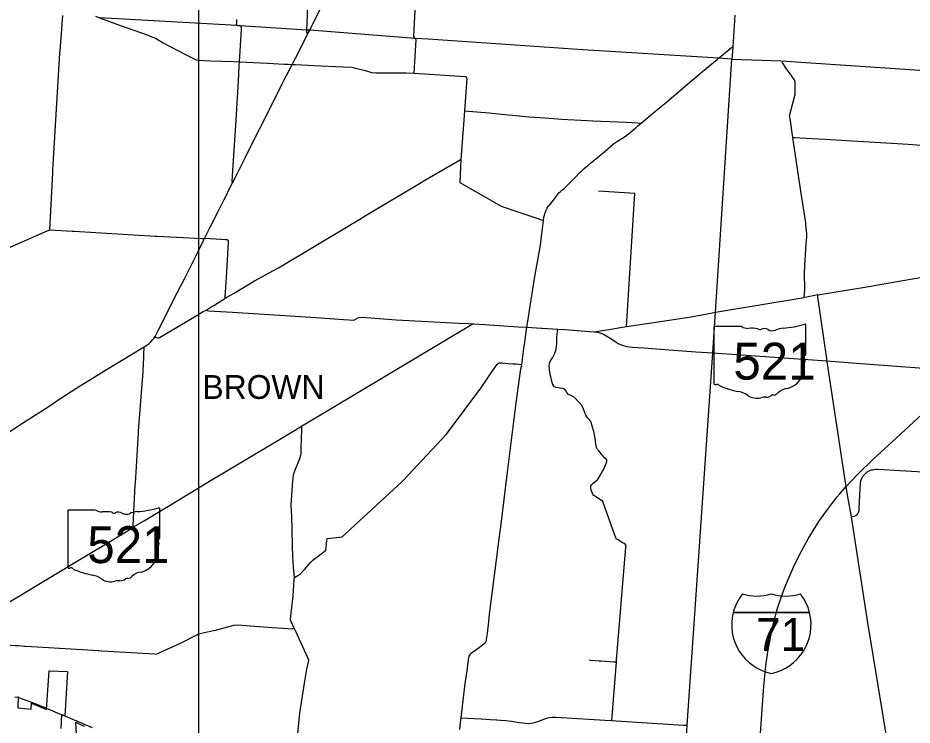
# Model space of a CAD drawing. Extents: x 1729596 to 1925846, y 659247 to 911751.
# Drawn here: x 1821771 to 1855559, y 833985 to 860705 of the extents above; entities that cross this region are included whole.
import ezdxf

# ---------------------------------------------------------------- set-up
doc = ezdxf.new("R2010")
doc.units = 0
for name, color, linetype in [('GM_X_Corporation', 7, 'Continuous'), ('GM_X_County', 7, 'Continuous'), ('GM_X_County_Road', 7, 'Continuous'), ('GM_X_Interstate_Route', 7, 'Continuous'), ('GM_X_Interstate_Shield', 7, 'Continuous'), ('GM_X_State_Route', 7, 'Continuous'), ('GM_X_State_Shield', 7, 'Continuous'), ('GM_X_Township', 7, 'Continuous'), ('GM_X_Township_Road', 7, 'Continuous'), ('GM_X_Township_Text', 7, 'Continuous'), ('GM_X_US_Route', 7, 'Continuous'), ('SH_Data', 7, 'Continuous')]:
    doc.layers.add(name, color=color, linetype=linetype)

msp = doc.modelspace()

# ---------------------------------------------------------------- linework, layer by layer
at = {"layer": 'GM_X_Corporation'}
for points in [[(1821656, 835046), (1821781, 835050), (1821769, 834633), (1822268, 834587), (1822281, 834808), (1822854, 834577), (1822956, 836039), (1823645, 836005), (1823540, 834336), (1823415, 834383), (1823397, 833851)], [(1824058, 832202), (1823955, 834094), (1824182, 833983), (1824200, 833986), (1824290, 833942)]]:
    msp.add_lwpolyline(points, dxfattribs=at)
at = {"layer": 'GM_X_County'}
msp.add_lwpolyline([(1848864, 860810), (1848787, 859601), (1848752, 859146), (1850615, 859080), (1861827, 858324)], dxfattribs=at)
at = {"layer": 'GM_X_County_Road'}
for points in [[(1824699, 860768), (1824857, 860710), (1825612, 860430), (1826656, 860059), (1826853, 859982), (1826971, 859934), (1827258, 859768), (1827710, 859527), (1828254, 859247), (1828432, 859153), (1828513, 859123), (1828584, 859112), (1829052, 859088), (1829917, 859051), (1830145, 859048), (1831204, 858991), (1831412, 858982), (1831846, 858956), (1831978, 858953), (1832140, 858950)], [(1848293, 859218), (1848788, 859619)], [(1832140, 858950), (1832225, 858943), (1832265, 858939), (1832961, 858909), (1834057, 858860), (1834388, 858837), (1834514, 858807), (1834697, 858768), (1834897, 858714), (1835014, 858675), (1835136, 858637), (1835294, 858625), (1835692, 858625), (1836196, 858623), (1836448, 858626), (1836739, 858621)], [(1841006, 849018), (1841051, 849314), (1841101, 849645), (1841295, 850857), (1841512, 852119), (1841560, 852444), (1841625, 853051), (1841645, 853178), (1841666, 853257), (1841678, 853296), (1841734, 853436), (1841775, 853522), (1841811, 853578), (1841852, 853630), (1841955, 853751), (1842050, 853872), (1842120, 853970), (1842174, 854044), (1842213, 854090), (1842257, 854132), (1842328, 854190), (1842398, 854247), (1842454, 854298), (1842569, 854408), (1842835, 854682), (1843009, 854858), (1843082, 854926), (1843184, 855026), (1843290, 855116), (1843408, 855218), (1843743, 855499), (1843955, 855674), (1844282, 855947), (1844355, 856000), (1844431, 856051), (1844597, 856149), (1844696, 856217), (1844777, 856277), (1844977, 856441), (1845142, 856580), (1845198, 856628), (1845320, 856733), (1845665, 857022), (1846093, 857374), (1846284, 857524), (1846382, 857614), (1847073, 858199), (1847645, 858684), (1848208, 859149), (1848243, 859177), (1848285, 859211), (1848293, 859218)], [(1852342, 847746), (1852332, 847819), (1852002, 850172), (1851992, 850242), (1851578, 850159), (1851485, 850140), (1851503, 850457), (1851507, 850519), (1851495, 850994), (1851492, 851085), (1851506, 851296), (1851510, 851368), (1851545, 851947), (1851548, 852007), (1851578, 852429), (1851584, 852517), (1851577, 852569), (1851568, 852637), (1851545, 852900), (1851540, 852956), (1851400, 853843), (1851390, 853908), (1851065, 856102), (1851052, 856192), (1850945, 856903), (1850930, 857004), (1851117, 857720), (1851136, 857792), (1851143, 857929), (1851137, 858286), (1851111, 858362), (1851070, 858431), (1851029, 858488), (1850952, 858587), (1850847, 858724), (1850809, 858773), (1850694, 858953), (1850650, 859027)], [(1836739, 858621), (1838675, 858491), (1838704, 858476), (1838715, 858460)], [(1838715, 858460), (1838725, 858446), (1838731, 858409), (1838644, 857189), (1838612, 856680), (1838509, 855352), (1838468, 854485), (1840033, 853588), (1840704, 853369), (1840998, 853268), (1841304, 853162), (1841625, 853051)], [(1851992, 850242), (1853696, 850524), (1855503, 850836), (1856828, 851059), (1859214, 851472), (1860807, 851754), (1861908, 851967)], [(1848128, 849585), (1851485, 850140)], [(1827483, 848845), (1828569, 849486), (1828773, 849606), (1828890, 849668)], [(1828890, 849668), (1828890, 849668), (1828924, 849648), (1828977, 849643), (1829879, 849585), (1833037, 849389), (1834076, 849311), (1834469, 849288), (1834642, 849380), (1834781, 849392), (1836063, 849299), (1838431, 849174), (1838783, 849153), (1838998, 849141)], [(1843595, 848838), (1843637, 848852), (1843852, 848894), (1844102, 848937), (1844768, 849049), (1846050, 849232), (1847118, 849400), (1847685, 849497), (1848128, 849585)], [(1846971, 832575), (1846971, 832575), (1847065, 833986), (1848030, 848046), (1848128, 849585)], [(1826954, 848664), (1826976, 848639), (1827002, 848628), (1827054, 848615), (1827084, 848617), (1827126, 848635), (1827483, 848845)], [(1838466, 833825), (1838487, 833985), (1838519, 834265), (1838567, 834705), (1838674, 835560), (1838743, 836040), (1838773, 836253), (1838796, 836429), (1838814, 836551), (1838826, 836590), (1838844, 836629), (1838867, 836664), (1838885, 836685), (1838954, 836740), (1839072, 836824), (1839157, 836890), (1839273, 836974), (1839413, 837081), (1839426, 837095), (1839438, 837110), (1839458, 837143), (1839466, 837161), (1839472, 837179), (1839477, 837198), (1839478, 837221), (1839510, 837440), (1839538, 837684), (1839547, 837760), (1839596, 838176), (1839967, 841111), (1840035, 841581), (1840259, 843439), (1840381, 844450), (1840596, 846166), (1840736, 847171), (1840762, 847354), (1840807, 847615), (1840906, 848311), (1840922, 848444), (1840955, 848656), (1841006, 849018)], [(1854821, 832136), (1854806, 832276), (1853927, 837618), (1853916, 837681), (1853270, 841855), (1853135, 842607), (1853071, 843001), (1853019, 843312), (1852359, 847640), (1852342, 847746)], [(1824834, 836804), (1824939, 836797), (1826941, 836673), (1827000, 836670), (1827915, 837079), (1827969, 837103), (1828528, 837401), (1828591, 837434), (1829159, 837555), (1829234, 837570), (1829847, 837731), (1829932, 837765), (1830068, 837770), (1831380, 837679), (1831789, 837651), (1832132, 837627), (1832164, 837633), (1832207, 837647), (1832086, 837925), (1832077, 837968), (1832081, 838107), (1832167, 838864), (1832211, 839479), (1832217, 839559), (1832354, 839640), (1832420, 839679), (1832530, 839793), (1832596, 839862), (1832843, 840137), (1832910, 840211), (1833329, 840531), (1833411, 840594), (1833446, 840962), (1833453, 841041), (1833926, 841092), (1834029, 841103), (1836280, 843180), (1836334, 843229), (1837952, 844970), (1838003, 845024), (1839263, 846719), (1839296, 846763), (1839657, 847296), (1839829, 847544), (1839890, 847618), (1839921, 847646), (1839949, 847661), (1839978, 847670), (1839994, 847672), (1840065, 847668), (1840312, 847648), (1840471, 847640), (1840580, 847631), (1840807, 847615)], [(1820825, 837049), (1820913, 837042), (1821680, 836994), (1821777, 836987), (1822028, 836972), (1822074, 836969)], [(1822074, 836969), (1824417, 836829)], [(1824417, 836829), (1824803, 836806), (1824834, 836804), (1824834, 836804)]]:
    msp.add_lwpolyline(points, dxfattribs=at)
at = {"layer": 'GM_X_Interstate_Route'}
for points in [[(1853497, 843457), (1854091, 844035), (1854810, 844689), (1856408, 846161), (1857196, 846884), (1857351, 847028)], [(1852825, 842723), (1853071, 843001), (1853486, 843445), (1853497, 843457)], [(1849960, 835440), (1849991, 835852), (1850027, 836225), (1850112, 836751), (1850219, 837345), (1850270, 837606), (1850358, 837993), (1850490, 838443), (1850609, 838810), (1850743, 839153), (1850946, 839662), (1851071, 839958), (1851303, 840416), (1851627, 841020), (1852032, 841680), (1852294, 842043), (1852715, 842598), (1852825, 842723)], [(1849232, 825823), (1849312, 826884), (1849342, 827283), (1849536, 829857), (1849737, 832422), (1849949, 835289), (1849960, 835440)]]:
    msp.add_lwpolyline(points, dxfattribs=at)
at = {"layer": 'GM_X_Interstate_Shield'}
for p, q in [((1848799, 838237), (1851684, 838237)), ((1851684, 838237), (1848799, 838237)), ((1851684, 838237), (1848799, 838237)), ((1848799, 838237), (1851684, 838237)), ((1851684, 838237), (1848799, 838237)), ((1851684, 838237), (1848799, 838237))]:
    msp.add_line(p, q, dxfattribs=at)
for centre, start, end in [((1850616, 837777), 141.669, 165.8066), ((1850616, 837777), 141.669, 165.8066), ((1849693, 840733), 253.0091, 286.9909), ((1849693, 840733), 253.0091, 286.9909), ((1850789, 840733), 253.0091, 286.9909), ((1850789, 840733), 253.0091, 286.9909), ((1849866, 837777), 14.1934, 38.331), ((1849866, 837777), 14.1934, 38.331), ((1850616, 837777), 165.8066, 258.463), ((1850616, 837777), 165.8066, 258.463), ((1849866, 837777), 281.537, 14.1934), ((1849866, 837777), 281.537, 14.1934)]:
    msp.add_arc(centre, 1875, start, end, dxfattribs=at)
at = {"layer": 'GM_X_State_Route'}
for points in [[(1824240, 840319), (1825270, 840939), (1826096, 841440), (1826142, 841474), (1826514, 841694), (1827976, 842576), (1829017, 843200), (1831719, 844816), (1832490, 845282), (1838868, 849097), (1838914, 849121), (1838998, 849141), (1839418, 849116)], [(1839418, 849116), (1839597, 849106), (1840678, 849037), (1841006, 849018)], [(1841006, 849018), (1841537, 848985), (1841586, 848982)], [(1841586, 848982), (1842167, 848948), (1842431, 848928)], [(1842431, 848928), (1843370, 848858), (1843543, 848843)], [(1843543, 848843), (1843595, 848838), (1843668, 848826), (1843754, 848804), (1843796, 848791), (1843824, 848782), (1843899, 848751), (1843959, 848721), (1844210, 848561), (1844336, 848473), (1844448, 848406), (1844608, 848336), (1844771, 848292), (1844988, 848267), (1845431, 848234), (1846221, 848181), (1847382, 848093), (1848030, 848046), (1852342, 847746), (1853462, 847664), (1857695, 847346)], [(1820468, 838053), (1820655, 838166), (1821648, 838759), (1824240, 840319)]]:
    msp.add_lwpolyline(points, dxfattribs=at)
at = {"layer": 'GM_X_State_Shield'}
for p, q in [((1851549, 847988), (1851549, 849093)), ((1851549, 847988), (1851549, 849093)), ((1848068, 849005), (1848068, 846891)), ((1848068, 849005), (1848068, 846891)), ((1849122, 849041), (1848102, 849041)), ((1849122, 849041), (1848102, 849041)), ((1851548, 847988), (1851549, 847988)), ((1851548, 847988), (1851549, 847988)), ((1823657, 842070), (1823657, 839957)), ((1823657, 842070), (1823657, 839957)), ((1824710, 842107), (1823691, 842107)), ((1824710, 842107), (1823691, 842107)), ((1827137, 841053), (1827137, 842159)), ((1827137, 841053), (1827137, 842159)), ((1827137, 841054), (1827137, 841053)), ((1827137, 841054), (1827137, 841053))]:
    msp.add_line(p, q, dxfattribs=at)
for centre, major_axis, start_param, end_param in [((1850309, 851922), (3691, 0), 4.814394, 5.042369), ((1850309, 851922), (3691, 0), 4.814394, 5.042369), ((1851510, 849098), (38.7, 0), 6.141152, 7.989035), ((1851510, 849098), (38.7, 0), 6.141152, 7.989035), ((1848108, 849009), (40.3, 0), 1.712693, 3.28349), ((1848108, 849009), (40.3, 0), 1.712693, 3.28349), ((1849364, 849286), (391, 0), 4.042523, 4.731795), ((1849364, 849286), (391, 0), 4.042523, 4.731795), ((1849494, 847855), (1404, 0), 1.404758, 1.657858), ((1849494, 847855), (1404, 0), 1.404758, 1.657858), ((1849813, 849020), (113, 0), 3.836095, 5.185415), ((1849813, 849020), (113, 0), 3.836095, 5.185415), ((1849978, 848776), (235, 0), 0.950623, 2.079405), ((1849978, 848776), (235, 0), 0.950623, 2.079405), ((1850281, 849111), (282, 0), 4.081561, 5.145723), ((1850281, 849111), (282, 0), 4.081561, 5.145723), ((1850780, 848395), (743, 0), 1.699011, 2.107814), ((1850780, 848395), (743, 0), 1.699011, 2.107814), ((1851540, 847907), (60, 0), 1.883978, 3.671073), ((1851540, 847907), (60, 0), 1.883978, 3.671073), ((1851158, 847767), (360, 0), 5.934695, 6.695948), ((1851158, 847767), (360, 0), 5.934695, 6.695948), ((1851507, 847984), (41.5, 0), 5.05454, 6.418171), ((1851507, 847984), (41.5, 0), 5.05454, 6.418171), ((1850515, 847385), (923, 0), 5.101752, 6.440018), ((1850515, 847385), (923, 0), 5.101752, 6.440018), ((1851687, 847525), (262, 0), 2.387724, 3.262537), ((1851687, 847525), (262, 0), 2.387724, 3.262537), ((1848108, 846887), (40.7, 0), 3.00124, 4.508301), ((1848108, 846887), (40.7, 0), 3.00124, 4.508301), ((1848115, 847103), (310, 0), 4.665946, 4.897461), ((1848115, 847103), (310, 0), 4.665946, 4.897461), ((1848178, 846769), (112, 0), 0.519207, 1.627899), ((1848178, 846769), (112, 0), 0.519207, 1.627899), ((1849591, 848668), (2665, 0), 4.195997, 4.488961), ((1849591, 848668), (2665, 0), 4.195997, 4.488961), ((1848797, 845942), (834, 0), 0.823519, 1.323587), ((1848797, 845942), (834, 0), 0.823519, 1.323587), ((1849699, 846759), (529, 0), 4.026481, 4.996735), ((1849699, 846759), (529, 0), 4.026481, 4.996735), ((1850043, 846601), (282, 0), 4.691044, 5.507374), ((1850043, 846601), (282, 0), 4.691044, 5.507374), ((1850298, 846396), (79.4, 0), 1.147584, 2.315152), ((1850298, 846396), (79.4, 0), 1.147584, 2.315152), ((1850264, 846686), (298, 0), 4.937069, 5.64225), ((1850264, 846686), (298, 0), 4.937069, 5.64225), ((1850905, 846298), (506, 0), 1.647645, 2.488434), ((1850905, 846298), (506, 0), 1.647645, 2.488434), ((1850004, 846028), (435, 0), 1.495662, 1.94098), ((1850004, 846028), (435, 0), 1.495662, 1.94098), ((1823697, 842075), (40.3, 0), 1.712693, 3.28349), ((1823697, 842075), (40.3, 0), 1.712693, 3.28349), ((1824953, 842352), (391, 0), 4.042523, 4.731795), ((1824953, 842352), (391, 0), 4.042523, 4.731795), ((1825083, 840920), (1404, 0), 1.404758, 1.657858), ((1825083, 840920), (1404, 0), 1.404758, 1.657858), ((1825402, 842086), (113, 0), 3.836095, 5.185415), ((1825402, 842086), (113, 0), 3.836095, 5.185415), ((1825567, 841841), (235, 0), 0.950623, 2.079405), ((1825567, 841841), (235, 0), 0.950623, 2.079405), ((1825870, 842176), (282, 0), 4.081561, 5.145723), ((1825870, 842176), (282, 0), 4.081561, 5.145723), ((1826368, 841461), (743, 0), 1.699011, 2.107814), ((1826368, 841461), (743, 0), 1.699011, 2.107814), ((1825898, 844988), (3691, 0), 4.814394, 5.042369), ((1825898, 844988), (3691, 0), 4.814394, 5.042369), ((1827099, 842163), (38.7, 0), 6.141152, 7.989035), ((1827099, 842163), (38.7, 0), 6.141152, 7.989035), ((1827128, 840972), (60, 0), 1.883978, 3.671073), ((1827128, 840972), (60, 0), 1.883978, 3.671073), ((1827096, 841049), (41.5, 0), 5.05454, 6.418171), ((1827096, 841049), (41.5, 0), 5.05454, 6.418171), ((1827276, 840591), (262, 0), 2.387724, 3.262537), ((1827276, 840591), (262, 0), 2.387724, 3.262537), ((1826747, 840833), (360, 0), 5.934695, 6.695948), ((1826747, 840833), (360, 0), 5.934695, 6.695948), ((1826104, 840450), (923, 0), 5.101752, 6.440018), ((1826104, 840450), (923, 0), 5.101752, 6.440018), ((1823697, 839952), (40.7, 0), 3.00124, 4.508301), ((1823697, 839952), (40.7, 0), 3.00124, 4.508301), ((1823703, 840168), (310, 0), 4.665946, 4.897461), ((1823703, 840168), (310, 0), 4.665946, 4.897461), ((1823767, 839835), (112, 0), 0.519207, 1.627899), ((1823767, 839835), (112, 0), 0.519207, 1.627899), ((1825180, 841734), (2665, 0), 4.195997, 4.488961), ((1825180, 841734), (2665, 0), 4.195997, 4.488961), ((1824385, 839008), (834, 0), 0.823519, 1.323587), ((1824385, 839008), (834, 0), 0.823519, 1.323587), ((1826494, 839364), (506, 0), 1.647645, 2.488434), ((1826494, 839364), (506, 0), 1.647645, 2.488434), ((1825287, 839824), (529, 0), 4.026481, 4.996735), ((1825287, 839824), (529, 0), 4.026481, 4.996735), ((1825593, 839094), (435, 0), 1.495662, 1.94098), ((1825593, 839094), (435, 0), 1.495662, 1.94098), ((1825632, 839666), (282, 0), 4.691044, 5.507374), ((1825632, 839666), (282, 0), 4.691044, 5.507374), ((1825887, 839462), (79.4, 0), 1.147584, 2.315152), ((1825887, 839462), (79.4, 0), 1.147584, 2.315152), ((1825853, 839752), (298, 0), 4.937069, 5.64225), ((1825853, 839752), (298, 0), 4.937069, 5.64225)]:
    msp.add_ellipse(centre, major_axis=major_axis, ratio=0.8, start_param=start_param, end_param=end_param, dxfattribs=at)
at = {"layer": 'GM_X_Township'}
for points in [[(1848864, 860810), (1848787, 859601), (1848752, 859146), (1848243, 859177), (1843111, 859493), (1837275, 859897), (1836785, 859928), (1833125, 860220), (1832799, 860239), (1832694, 860243), (1830166, 860402), (1830089, 860410), (1830057, 860416), (1824857, 860710)], [(1858606, 831851), (1854821, 832136), (1851310, 832334), (1849737, 832422), (1846971, 832575), (1847065, 833986), (1848030, 848046), (1848128, 849585), (1848752, 859146), (1850615, 859080), (1861827, 858324)]]:
    msp.add_lwpolyline(points, dxfattribs=at)
at = {"layer": 'GM_X_Township_Road'}
for points in [[(1832712, 860086), (1832692, 860180), (1832694, 860243), (1832711, 860815), (1832717, 860894), (1832916, 864638), (1832920, 864735), (1833003, 866422), (1833008, 866525), (1833111, 868476), (1833115, 868570)], [(1836801, 859906), (1836785, 859928), (1836730, 860003), (1836772, 860771), (1836832, 861759), (1836900, 861806), (1837774, 861777), (1841815, 864609), (1841870, 865582)], [(1822973, 852697), (1823090, 854855), (1823095, 854950), (1823360, 859378), (1823364, 859462), (1823464, 860797)], [(1830145, 859048), (1830219, 860280), (1830222, 860351), (1830198, 860382), (1830166, 860402), (1830089, 860410), (1830057, 860416), (1830033, 860449), (1830040, 860509), (1830047, 860642)], [(1836739, 858621), (1836819, 859882), (1836801, 859906)], [(1829879, 854468), (1829867, 854539), (1829884, 854733), (1829968, 856079), (1830015, 856843), (1830104, 858325), (1830133, 858863), (1830135, 858890)], [(1830135, 858890), (1830145, 859048)], [(1838644, 857189), (1839578, 857114), (1840298, 857042)], [(1840298, 857042), (1840462, 857025), (1841078, 856968), (1841688, 856928), (1842311, 856878), (1843277, 856832), (1843501, 856817), (1844772, 856764), (1845200, 856735), (1845320, 856733)], [(1851052, 856192), (1851109, 856192), (1851317, 856179), (1852272, 856121), (1852677, 856096), (1855405, 855928), (1855903, 855897), (1856892, 855832)], [(1834871, 853208), (1837006, 854484), (1837090, 854534), (1838463, 855326), (1838509, 855352)], [(1844768, 849049), (1845076, 854067), (1843711, 854157), (1843711, 854157)], [(1829632, 850131), (1829670, 850148), (1829937, 850308), (1830715, 850775), (1831571, 851235), (1831618, 851263), (1834382, 852917), (1834467, 852967), (1834850, 853196), (1834871, 853208)], [(1821238, 851978), (1821378, 852020), (1821474, 852048), (1822880, 852657), (1822973, 852697), (1822981, 852696), (1823816, 852647), (1823896, 852643), (1826953, 852461), (1827020, 852457), (1827766, 852423)], [(1827766, 852423), (1827772, 852422), (1828724, 852374), (1828817, 852370)], [(1829609, 850120), (1829604, 850137), (1829602, 850154), (1829661, 851097), (1829717, 852021), (1829733, 852247), (1829733, 852268), (1829728, 852285), (1829722, 852293), (1829709, 852307), (1829695, 852315), (1829689, 852317), (1829659, 852321), (1829617, 852324), (1829269, 852344), (1829020, 852358), (1828817, 852370)], [(1828890, 849668), (1829079, 849784), (1829169, 849839), (1829310, 849931), (1829553, 850077), (1829575, 850092), (1829609, 850120), (1829632, 850131)], [(1843111, 845983), (1843107, 845993), (1843076, 846068), (1843002, 846144), (1842938, 846209), (1842834, 846328), (1842792, 846377), (1842745, 846400), (1842658, 846443), (1842580, 846479), (1842518, 846549), (1842493, 846596), (1842466, 846646), (1842396, 846696), (1842344, 846704), (1842246, 846720), (1842194, 846729), (1842110, 846744), (1842034, 846776), (1842009, 846822), (1841976, 846884), (1841907, 847139), (1841882, 847229), (1841869, 847334), (1841860, 847401), (1841852, 847454), (1841840, 847528), (1841863, 847661), (1841896, 847749), (1841968, 847865), (1842022, 847959), (1842058, 848032), (1842084, 848101), (1842105, 848172), (1842112, 848208), (1842126, 848296), (1842134, 848374), (1842137, 848623), (1842150, 848766), (1842167, 848948)], [(1826484, 847033), (1826485, 847041), (1826492, 847131), (1826529, 847868), (1826535, 848025), (1826539, 848226), (1826523, 848267)], [(1826142, 841474), (1826131, 841521), (1826129, 841545), (1826206, 843055), (1826209, 843120), (1826326, 845018), (1826330, 845093), (1826484, 847033)], [(1843823, 844224), (1843717, 844351), (1843674, 844402), (1843630, 844475), (1843602, 844684), (1843594, 844739), (1843558, 844947), (1843544, 845028), (1843460, 845334), (1843438, 845415), (1843386, 845501), (1843361, 845526), (1843349, 845538), (1843298, 845589), (1843268, 845633), (1843228, 845691), (1843209, 845741), (1843188, 845798), (1843111, 845983)], [(1832217, 839559), (1832181, 839958), (1832166, 840360), (1832150, 840747), (1832131, 841365), (1832119, 841876), (1832100, 842311), (1832130, 842865), (1832154, 843199), (1832190, 843436), (1832231, 843590), (1832429, 844063), (1832467, 844186), (1832471, 844240), (1832481, 844468), (1832506, 845131), (1832505, 845224), (1832490, 845282)], [(1843771, 843420), (1843860, 843570), (1843863, 843575), (1843892, 843625), (1843997, 843867), (1844030, 843945), (1844022, 844005), (1843954, 844068), (1843823, 844224)], [(1843677, 842566), (1843609, 842613), (1843559, 842648), (1843513, 842674), (1843503, 842690), (1843491, 842712), (1843453, 842794), (1843429, 842865), (1843423, 842949), (1843423, 843023), (1843441, 843067), (1843499, 843117), (1843540, 843150), (1843617, 843209), (1843675, 843258), (1843771, 843420)], [(1853270, 841855), (1853375, 841876), (1853430, 841904), (1853489, 841960), (1853510, 841987), (1853529, 842020), (1853540, 842047), (1853556, 842102), (1853564, 842152), (1853571, 842416), (1853597, 842931), (1853607, 843104), (1853625, 843215), (1853660, 843313), (1853709, 843404), (1853779, 843484), (1853838, 843531), (1853844, 843535)], [(1853844, 843535), (1853861, 843548), (1853911, 843579), (1853965, 843605), (1854028, 843627), (1854060, 843636), (1854125, 843648), (1854191, 843655), (1854258, 843655), (1854503, 843639), (1854896, 843613), (1855969, 843548)], [(1844215, 834160), (1844384, 836360), (1844385, 836371), (1844391, 836449), (1844748, 840708), (1844751, 840754), (1844719, 840820), (1844674, 840847), (1844607, 840886), (1844427, 840996), (1844381, 841024), (1844362, 841073), (1844329, 841160), (1844136, 841693), (1843898, 842352), (1843869, 842432), (1843677, 842566)], [(1832327, 833414), (1832426, 834435), (1832607, 835575), (1832687, 836093), (1832759, 836431), (1832731, 836526), (1832414, 837215), (1832308, 837446), (1832207, 837647)], [(1843367, 836442), (1843417, 836439), (1843733, 836416), (1843809, 836411), (1844283, 836378), (1844385, 836371)], [(1838519, 834265), (1839003, 834239), (1839280, 834220), (1839610, 834202), (1839845, 834186), (1839872, 834185)], [(1839872, 834185), (1840004, 834176), (1840213, 834155), (1840314, 834142), (1840419, 834128), (1840709, 834086), (1840854, 834066), (1840955, 834057), (1841058, 834052), (1841152, 834058), (1841236, 834072), (1841340, 834101), (1841488, 834149), (1841639, 834205), (1841751, 834242), (1841801, 834256), (1841870, 834271), (1841962, 834284), (1842018, 834287), (1842093, 834287), (1842280, 834278)], [(1842280, 834278), (1842320, 834277), (1843950, 834176), (1844215, 834160), (1844383, 834149), (1846926, 833987), (1847065, 833986)]]:
    msp.add_lwpolyline(points, dxfattribs=at)
at = {"layer": 'GM_X_US_Route'}
for points in [[(1832814, 860270), (1833045, 860728), (1833707, 862039), (1833995, 862623), (1834269, 863162), (1835215, 865051), (1835681, 865996), (1836078, 866774), (1836442, 867502), (1837331, 869279), (1837642, 869882), (1838022, 870648), (1838475, 871555), (1838873, 872351), (1839135, 872864), (1840316, 875226), (1840905, 876404)], [(1830354, 855412), (1830390, 855482), (1830910, 856524), (1831328, 857349), (1831761, 858212), (1831835, 858364), (1831922, 858529), (1832140, 858950), (1832178, 859024), (1832261, 859187), (1832516, 859678), (1832712, 860086), (1832799, 860239), (1832814, 860270)], [(1829567, 853847), (1829623, 853958), (1829773, 854260), (1829879, 854468), (1830065, 854836), (1830354, 855412)], [(1828794, 852323), (1828817, 852370), (1829042, 852803), (1829388, 853493), (1829567, 853847)], [(1826523, 848267), (1826643, 848340), (1826727, 848406), (1826792, 848465), (1826862, 848537), (1826902, 848592), (1826954, 848664), (1827089, 848914), (1827795, 850319), (1828063, 850849), (1828568, 851857), (1828794, 852323)], [(1815985, 842997), (1816140, 843045), (1816516, 843159), (1818004, 843604), (1819466, 844036), (1819970, 844186), (1820078, 844226), (1820154, 844261), (1820230, 844302), (1820378, 844395), (1820678, 844582), (1820789, 844650), (1821371, 845021), (1821564, 845146), (1821850, 845326), (1822366, 845660), (1822875, 845990), (1823392, 846332), (1823964, 846703), (1824557, 847070), (1825025, 847354), (1825562, 847681), (1826103, 848010), (1826523, 848267)], [(1821742, 835058), (1821837, 835019), (1821938, 834981)], [(1821938, 834981), (1822282, 834851), (1822381, 834811)], [(1822381, 834811), (1822857, 834621), (1822968, 834573)], [(1822968, 834573), (1823279, 834440), (1823404, 834391), (1823504, 834351)], [(1823504, 834351), (1823539, 834337), (1823602, 834310)], [(1823602, 834310), (1823863, 834198), (1823927, 834172), (1823961, 834158), (1824572, 833896)]]:
    msp.add_lwpolyline(points, dxfattribs=at)
at = {"layer": 'SH_Data'}
msp.add_line((1828599, 890928), (1828599, 814428), dxfattribs=at)

# ---------------------------------------------------------------- texts
at = {"layer": 'GM_X_Interstate_Shield'}
msp.add_text('71', height=1250, dxfattribs=at).set_placement((1849664, 836784))
msp.add_text('71', height=1250, dxfattribs=at).set_placement((1849664, 836784))
at = {"layer": 'GM_X_State_Shield'}
for p in [(1848805, 847040), (1848805, 847040), (1824394, 840106), (1824394, 840106)]:
    msp.add_text('521', height=1392.2, dxfattribs=at).set_placement(p)
at = {"layer": 'GM_X_Township_Text'}
msp.add_text('BROWN', height=900, rotation=0, dxfattribs=at).set_placement((1828743, 846310))

doc.saveas('drawing.dxf')
